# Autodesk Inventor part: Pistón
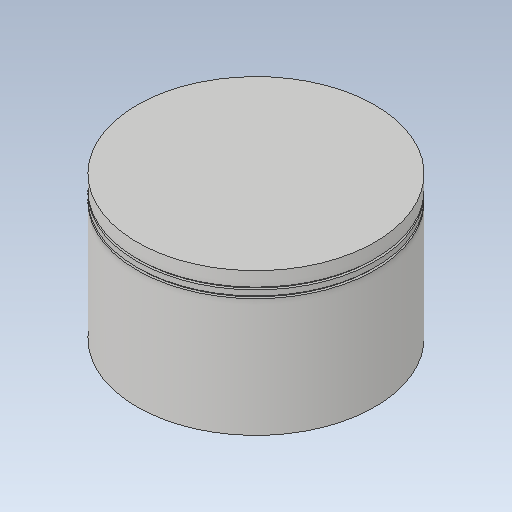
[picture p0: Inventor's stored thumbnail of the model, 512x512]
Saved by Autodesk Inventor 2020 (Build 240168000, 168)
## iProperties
Created: 2019-09
Part Number: Pistón
Material: Generic
Document SubType Name: Modeling
Designer: user
Density: 1 g/cm^3
Appearance: Default
Mass: 13.7671 g
Surface Area: 152.075 cm^2
Volume: 13.7671 cm^3
Author: user
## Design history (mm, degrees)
sketch "Sketch1"
  geometry: C1 r 25 at (0, 0); 1 further point
  constraints: 1 centre point, 1 coincident
  dimensions: "d0" = 50 diameter of C1
extrude "Extrusion1" new body sketch "Sketch1" stored distance "d1" = 30; taper "d2" = 0 deg
shell "Shell1" dims "d3" = 1
sketch "Sketch2"
  geometry: C1 r 5 at (0, 0); 1 further point
  constraints: 1 centre point, 1 coincident
  dimensions: "d4" = 10 diameter of C1
extrude "Extrusion2" join sketch "Sketch2" stored distance "d5" = 10; taper "d6" = 0 deg
sketch "Sketch3"
  geometry: C1 r 5 at (0, 0) reference; C2 r 7.5 at (0, 0); 1 further point
  constraints: 1 centre point, 1 coincident
  dimensions: "d7" = 15 diameter of C2
extrude "Extrusion3" join sketch "Sketch3" stored distance "d8" = 10; taper "d9" = 0 deg
sketch "Sketch4"
  geometry: C1 r 5 at (0, 0) reference; C2 r 7.5 at (0, 0); 1 further point
  constraints: 1 centre point, 1 coincident
  dimensions: "d10" = 15 diameter of C2
extrude "Extrusion4" join sketch "Sketch4" stored distance "d11" = 10; taper "d12" = 0 deg
sketch "Sketch5"
  geometry: L1 (20.41, 0)-(8.768, 0); L2 (-15, 25)-(15, 25) reference; L3 (12, 25)-(12, 24.5); L4 (12, 24.5)-(11.5, 24.5); L5 (11.5, 24.5)-(11.5, 25); L6 (12, 25)-(11.75, 25.88); L7 (11.75, 25.88)-(11.5, 25); L8 (10.401, 25)-(10.401, 24.5); L9 (10.401, 24.5)-(9.901, 24.5); L10 (9.901, 24.5)-(9.901, 25); L11 (10.401, 25)-(10.151, 25.88); L12 (10.151, 25.88)-(9.901, 25); 1 further point
  constraints: 22 end point, 4 perpendicular, 2 point on line, 2 vertical, 1 horizontal
  dimensions: "d13" = 0.5 distance of L3.start L3.end; "d14" = 0.5 distance of L3.end L4.end; "d15" = 0.5 distance of L8.start L8.end; "d16" = 0.5 distance of L8.end L9.end
revolve "Revolution1" sketch "Sketch5" stored, may be unused: angle "d17" = 90 deg
body "Solid1"
